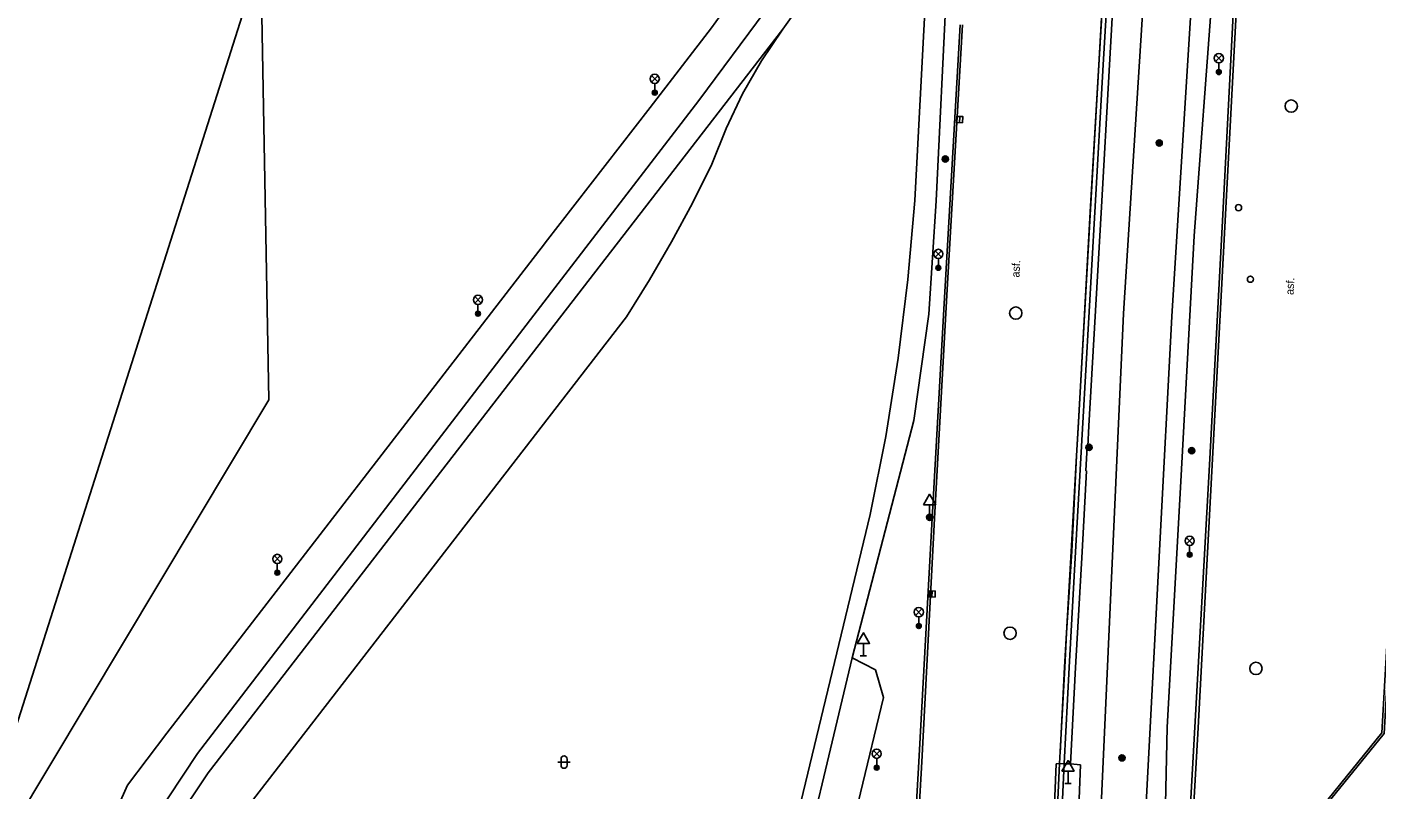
# Model space of a CAD drawing. Extents: x -599951 to -598963, y -1164095 to -1162939.
# Drawn here: x -599271.4 to -599161.8, y -1164038.6 to -1163976.7 of the extents above; entities that cross this region are included whole.
import ezdxf

# ---------------------------------------------------------------- set-up
doc = ezdxf.new("R2010")
doc.units = 0
for name, color, linetype in [('Level 10', 7, 'Continuous'), ('Level 11', 7, 'Continuous'), ('Level 13', 7, 'Continuous'), ('Level 25', 7, 'Continuous'), ('Level 27', 7, 'Continuous'), ('Level 28', 7, 'Continuous'), ('Level 33', 7, 'Continuous'), ('Level 34', 7, 'Continuous'), ('Level 36', 7, 'Continuous'), ('Level 40', 7, 'Continuous'), ('Level 9', 7, 'Continuous')]:
    doc.layers.add(name, color=color, linetype=linetype)

msp = doc.modelspace()

# ---------------------------------------------------------------- linework, layer by layer
at = {"layer": 'Level 10'}
for points in [[(-599173.23, -1163971.43), (-599174.29, -1163991.9), (-599175.35, -1164011.75), (-599176.55, -1164033.54), (-599177.56, -1164051.44), (-599178.64, -1164071.21)], [(-599196.92, -1163999.13), (-599195.62, -1163976.51)], [(-599196.92, -1163999.13), (-599197.89, -1164016.58)], [(-599159.94, -1164012.34), (-599161.18, -1164034.05), (-599165.51, -1164039.38)], [(-599197.89, -1164016.58), (-599198.98, -1164036.35), (-599199.45, -1164044.34), (-599199.93, -1164050.44), (-599200.67, -1164056.43), (-599201.53, -1164060.7), (-599202.85, -1164065), (-599204.64, -1164069.23), (-599206.88, -1164073.31), (-599208.33, -1164076.09), (-599209.5, -1164077.88), (-599210.81, -1164079.56), (-599212.22, -1164081.1), (-599214.37, -1164083.05)], [(-599190.59, -1164094.69), (-599190.42, -1164091.32), (-599188.5, -1164057.11), (-599187.54, -1164036.49)]]:
    msp.add_lwpolyline(points, dxfattribs=at)
at = {"layer": 'Level 11'}
for points in [[(-599172.9, -1163813.11), (-599173.38, -1163820.1), (-599174.07, -1163830.07), (-599174.74, -1163840.04), (-599175.4, -1163850), (-599175.95, -1163858.03), (-599176.47, -1163865.91), (-599177.1, -1163875.95), (-599177.75, -1163885.93), (-599178.52, -1163897.89), (-599179.3, -1163909.98), (-599179.92, -1163919.81), (-599180.51, -1163929.76), (-599181.12, -1163939.81), (-599181.72, -1163949.74), (-599182.32, -1163959.77), (-599182.91, -1163969.7), (-599183.49, -1163979.74), (-599184.17, -1163991.77), (-599185.17, -1164009.07), (-599185.26, -1164010.75)], [(-599172.9, -1163813.11), (-599173.38, -1163820.1), (-599174.07, -1163830.07), (-599174.74, -1163840.04), (-599175.4, -1163850), (-599175.95, -1163858.03), (-599176.47, -1163865.91), (-599177.1, -1163875.95), (-599177.75, -1163885.93), (-599178.52, -1163897.89), (-599179.3, -1163909.98), (-599179.92, -1163919.81), (-599180.51, -1163929.76), (-599181.12, -1163939.81), (-599181.72, -1163949.74), (-599182.32, -1163959.77), (-599182.91, -1163969.7), (-599183.49, -1163979.74), (-599184.17, -1163991.77), (-599185.17, -1164009.07), (-599185.26, -1164010.75)], [(-599186.16, -1164011.52), (-599186, -1164008.75), (-599185.03, -1163991.47), (-599184.35, -1163979.77), (-599183.76, -1163969.76), (-599183.18, -1163959.77), (-599182.58, -1163949.77), (-599181.98, -1163939.79), (-599181.35, -1163929.78), (-599180.76, -1163919.85), (-599180.56, -1163916.59)], [(-599173.97, -1163953.72), (-599175.11, -1163973.69), (-599176.62, -1163993.64)], [(-599288.18, -1164067.68), (-599277.59, -1164050.01), (-599272.53, -1164041.57), (-599251.79, -1164006.95), (-599252.73, -1163954.94)], [(-599288.18, -1164067.68), (-599277.59, -1164050.01), (-599272.53, -1164041.57), (-599251.79, -1164006.95), (-599252.73, -1163954.94)], [(-599272.69, -1163964.01), (-599294.28, -1164045.51), (-599277.59, -1164050.01), (-599252.44, -1163970.97)], [(-599178.38, -1164071.18), (-599177.31, -1164051.48), (-599176.3, -1164033.6), (-599175.12, -1164011.76), (-599174.06, -1163991.91), (-599172.98, -1163971.45)], [(-599196.72, -1163973.49), (-599197.56, -1163990.8), (-599198.17, -1163999.99)], [(-599247.79, -1164081.46), (-599251.56, -1164079.78), (-599256.02, -1164076.8), (-599259.29, -1164073.61), (-599262.33, -1164069.95), (-599264.74, -1164065.27), (-599266.14, -1164060.83), (-599266.79, -1164058.45), (-599267.31, -1164056.55), (-599267.39, -1164055.11), (-599267.51, -1164052.79), (-599267.55, -1164052.03), (-599267.32, -1164050.55), (-599266.92, -1164047.98), (-599265.6, -1164043.54), (-599263.26, -1164038.24), (-599260.07, -1164034.03), (-599229.39, -1163994.3), (-599229.33, -1163994.22), (-599220.81, -1163983.21), (-599215.82, -1163976.75), (-599214.4, -1163974.81)], [(-599247.79, -1164081.46), (-599251.56, -1164079.78), (-599256.02, -1164076.8), (-599259.29, -1164073.61), (-599262.33, -1164069.95), (-599264.74, -1164065.27), (-599266.14, -1164060.83), (-599266.79, -1164058.45), (-599267.31, -1164056.55), (-599267.39, -1164055.11), (-599267.51, -1164052.79), (-599267.55, -1164052.03), (-599267.32, -1164050.55), (-599266.92, -1164047.98), (-599265.6, -1164043.54), (-599263.26, -1164038.24), (-599260.07, -1164034.03), (-599229.39, -1163994.3), (-599229.33, -1163994.22), (-599220.81, -1163983.21), (-599215.82, -1163976.75), (-599214.4, -1163974.81)], [(-599211.47, -1163975.39), (-599216.86, -1163982.64), (-599230.24, -1164000.07), (-599257.58, -1164035.67), (-599261.16, -1164041.12), (-599262.87, -1164045.41), (-599264.04, -1164049.93), (-599264.28, -1164054.68), (-599263.81, -1164059.27), (-599262.56, -1164063.71), (-599259.99, -1164068.39), (-599256.72, -1164072.83), (-599254.73, -1164074.44)], [(-599195.43, -1163976.51), (-599196.69, -1163998.47)], [(-599176.62, -1163993.64), (-599177.69, -1164013.59), (-599178.8, -1164033.53)], [(-599197.7, -1164016.59), (-599196.69, -1163998.47)], [(-599198.17, -1163999.99), (-599199.37, -1164008.64), (-599204.39, -1164027.91)], [(-599185.41, -1164012.73), (-599185.31, -1164010.75)], [(-599185.26, -1164010.75), (-599185.31, -1164010.75)], [(-599186.97, -1164025.89), (-599186.6, -1164019.28), (-599186.16, -1164011.52)], [(-599165.72, -1164039.39), (-599161.36, -1164033.99), (-599160.13, -1164012.32)], [(-599185.36, -1164012.73), (-599185.72, -1164019.29), (-599186.25, -1164028.71), (-599186.67, -1164036.53)], [(-599185.36, -1164012.73), (-599185.41, -1164012.73)], [(-599197.7, -1164016.59), (-599198.73, -1164036.37), (-599199.2, -1164044.36)], [(-599187.54, -1164036.49), (-599187.12, -1164028.69), (-599186.97, -1164025.89)], [(-599209.56, -1164049.62), (-599204.39, -1164027.91)], [(-599202.5, -1164028.88), (-599204.39, -1164027.91)], [(-599201.85, -1164031.13), (-599202.5, -1164028.88)], [(-599205.58, -1164046.62), (-599201.85, -1164031.13)], [(-599178.8, -1164033.53), (-599179.01, -1164043.52), (-599179.62, -1164053.5), (-599180.52, -1164073.51), (-599181.2, -1164093.53), (-599181.24, -1164094.69)], [(-599190.81, -1164094.69), (-599190.53, -1164089.3), (-599188.66, -1164057.07), (-599187.81, -1164036.53), (-599187.54, -1164036.49)], [(-599187.18, -1164036.51), (-599187.54, -1164036.49)], [(-599187.29, -1164073.1), (-599185.85, -1164036.61), (-599186.67, -1164036.53)], [(-599186.67, -1164036.53), (-599187.18, -1164036.51)]]:
    msp.add_lwpolyline(points, dxfattribs=at)
at = {"layer": 'Level 13'}
msp.add_line((-599186.64, -1164094.69), (-599182.35, -1163999.95), dxfattribs=at)
for points in [[(-599178.43, -1164000.2), (-599167.24, -1163821.2)], [(-599173.6, -1163862.17), (-599182.35, -1163999.95)], [(-599193.21, -1163875.57), (-599199.31, -1163990.76)], [(-599201.8, -1163953.59), (-599202.01, -1163956.72), (-599202.47, -1163959.82), (-599203.16, -1163962.87), (-599204.09, -1163965.87), (-599205.25, -1163968.78), (-599206.63, -1163971.59), (-599208.22, -1163974.29), (-599210.02, -1163976.85)], [(-599210.02, -1163976.85), (-599256.7, -1164037.24)], [(-599210.02, -1163976.85), (-599211.75, -1163979.43), (-599213.3, -1163982.12), (-599214.64, -1163984.92), (-599215.78, -1163987.81), (-599217.37, -1163990.99), (-599219.06, -1163994.12), (-599220.85, -1163997.2), (-599222.73, -1164000.22)], [(-599202.93, -1164016.26), (-599201.67, -1164009.94), (-599200.65, -1164003.58), (-599199.86, -1163997.18), (-599199.31, -1163990.76)], [(-599253.47, -1164039.98), (-599222.73, -1164000.22)], [(-599181.42, -1164057.19), (-599178.43, -1164000.2)], [(-599210.01, -1164045.6), (-599202.93, -1164016.26)], [(-599212.79, -1164057.11), (-599213.94, -1164061.16), (-599215.67, -1164064.99), (-599217.96, -1164068.51), (-599220.74, -1164071.67), (-599223.96, -1164074.37), (-599227.54, -1164076.56), (-599231.41, -1164078.2), (-599235.49, -1164079.25), (-599240.42, -1164078.89), (-599245.24, -1164077.72), (-599249.79, -1164075.77), (-599253.95, -1164073.08), (-599257.29, -1164069.43), (-599259.89, -1164065.22), (-599261.64, -1164060.59), (-599262.49, -1164055.71), (-599262.4, -1164050.76), (-599261.37, -1164045.92), (-599259.45, -1164041.35), (-599256.7, -1164037.24)]]:
    msp.add_lwpolyline(points, dxfattribs=at)
at = {"layer": 'Level 25'}
for centre, radius in [((-599179.45, -1163986.1), 0.25), ((-599179.45, -1163986.1), 0.2), ((-599179.45, -1163986.1), 0.15), ((-599179.45, -1163986.1), 0.1), ((-599179.45, -1163986.1), 0.05), ((-599196.83, -1163987.4), 0.25), ((-599196.83, -1163987.4), 0.2), ((-599196.83, -1163987.4), 0.15), ((-599196.83, -1163987.4), 0.1), ((-599196.83, -1163987.4), 0.05), ((-599185.15, -1164010.82), 0.25), ((-599185.15, -1164010.82), 0.2), ((-599185.15, -1164010.82), 0.15), ((-599185.15, -1164010.82), 0.1), ((-599185.15, -1164010.82), 0.05), ((-599176.81, -1164011.09), 0.25), ((-599176.81, -1164011.09), 0.2), ((-599176.81, -1164011.09), 0.15), ((-599176.81, -1164011.09), 0.1), ((-599176.81, -1164011.09), 0.05), ((-599198.1, -1164016.5), 0.25), ((-599198.1, -1164016.5), 0.2), ((-599198.1, -1164016.5), 0.15), ((-599198.1, -1164016.5), 0.1), ((-599198.1, -1164016.5), 0.05), ((-599182.48, -1164036.04), 0.25), ((-599182.48, -1164036.04), 0.2), ((-599182.48, -1164036.04), 0.15), ((-599182.48, -1164036.04), 0.1), ((-599182.48, -1164036.04), 0.05)]:
    msp.add_circle(centre, radius, dxfattribs=at)
at = {"layer": 'Level 27'}
for p, q in [((-599195.67, -1163984.45), (-599195.65, -1163983.95)), ((-599197.91, -1164022.98), (-599197.89, -1164022.48))]:
    msp.add_line(p, q, dxfattribs=at)
for points in [[(-599195.42, -1163984.46), (-599195.4, -1163983.96), (-599195.9, -1163983.94), (-599195.92, -1163984.44)], [(-599197.66, -1164022.99), (-599197.64, -1164022.49), (-599198.14, -1164022.47), (-599198.16, -1164022.97)]]:
    msp.add_lwpolyline(points, close=True, dxfattribs=at)
for centre in [(-599168.73, -1163983.1), (-599191.1, -1163999.91), (-599191.57, -1164025.91), (-599171.59, -1164028.77)]:
    msp.add_circle(centre, 0.5, dxfattribs=at)
at = {"layer": 'Level 28'}
for centre in [(-599173.01, -1163991.35), (-599172.04, -1163997.16)]:
    msp.add_circle(centre, 0.25, dxfattribs=at)
at = {"layer": 'Level 33'}
for p, q in [((-599174.87, -1163979.48), (-599174.34, -1163978.95)), ((-599174.87, -1163978.95), (-599174.34, -1163979.48)), ((-599220.69, -1163981.15), (-599220.16, -1163980.62)), ((-599220.69, -1163980.62), (-599220.16, -1163981.15)), ((-599174.61, -1163979.59), (-599174.61, -1163980.34)), ((-599220.43, -1163981.26), (-599220.43, -1163982.01)), ((-599197.66, -1163995.38), (-599197.13, -1163994.85)), ((-599197.66, -1163994.85), (-599197.13, -1163995.38)), ((-599197.39, -1163995.49), (-599197.39, -1163996.24)), ((-599235.05, -1163999.1), (-599234.52, -1163998.57)), ((-599235.05, -1163998.57), (-599234.52, -1163999.1)), ((-599234.79, -1163999.21), (-599234.79, -1163999.96)), ((-599177.25, -1164018.67), (-599176.72, -1164018.14)), ((-599177.25, -1164018.14), (-599176.72, -1164018.67)), ((-599176.98, -1164018.78), (-599176.98, -1164019.53)), ((-599251.35, -1164020.14), (-599250.82, -1164019.61)), ((-599251.35, -1164019.61), (-599250.82, -1164020.14)), ((-599251.09, -1164020.25), (-599251.09, -1164021)), ((-599199.25, -1164024.47), (-599198.72, -1164023.94)), ((-599199.25, -1164023.94), (-599198.72, -1164024.47)), ((-599198.98, -1164024.58), (-599198.98, -1164025.33)), ((-599202.66, -1164035.97), (-599202.13, -1164035.44)), ((-599202.66, -1164035.44), (-599202.13, -1164035.97)), ((-599202.4, -1164036.08), (-599202.4, -1164036.83))]:
    msp.add_line(p, q, dxfattribs=at)
for centre, radius in [((-599174.61, -1163979.21), 0.375), ((-599220.43, -1163980.89), 0.375), ((-599174.61, -1163980.34), 0.2), ((-599174.61, -1163980.34), 0.145), ((-599174.61, -1163980.34), 0.0876), ((-599220.43, -1163982.01), 0.2), ((-599220.43, -1163982.01), 0.145), ((-599220.43, -1163982.01), 0.0876), ((-599197.39, -1163995.11), 0.375), ((-599197.39, -1163996.24), 0.2), ((-599197.39, -1163996.24), 0.145), ((-599197.39, -1163996.24), 0.0876), ((-599234.79, -1163998.84), 0.375), ((-599234.79, -1163999.96), 0.2), ((-599234.79, -1163999.96), 0.145), ((-599234.79, -1163999.96), 0.0876), ((-599176.98, -1164018.41), 0.375), ((-599251.09, -1164019.88), 0.375), ((-599176.98, -1164019.53), 0.2), ((-599176.98, -1164019.53), 0.145), ((-599176.98, -1164019.53), 0.0876), ((-599251.09, -1164021), 0.2), ((-599251.09, -1164021), 0.145), ((-599251.09, -1164021), 0.0876), ((-599198.98, -1164024.2), 0.375), ((-599198.98, -1164025.33), 0.2), ((-599198.98, -1164025.33), 0.145), ((-599198.98, -1164025.33), 0.0876), ((-599202.4, -1164035.7), 0.375), ((-599202.4, -1164036.83), 0.2), ((-599202.4, -1164036.83), 0.145), ((-599202.4, -1164036.83), 0.0876)]:
    msp.add_circle(centre, radius, dxfattribs=at)
at = {"layer": 'Level 34'}
for p, q in [((-599198.1, -1164015.48), (-599198.1, -1164016.5)), ((-599198.35, -1164016.5), (-599197.85, -1164016.5)), ((-599203.73, -1164027.76), (-599203.23, -1164027.76)), ((-599203.48, -1164026.74), (-599203.48, -1164027.76)), ((-599186.86, -1164037.11), (-599186.86, -1164038.13)), ((-599187.11, -1164038.13), (-599186.61, -1164038.13))]:
    msp.add_line(p, q, dxfattribs=at)
for points in [[(-599198.6, -1164015.48), (-599197.6, -1164015.48), (-599198.1, -1164014.62)], [(-599203.98, -1164026.74), (-599202.98, -1164026.74), (-599203.48, -1164025.88)], [(-599187.36, -1164037.11), (-599186.36, -1164037.11), (-599186.86, -1164036.25)]]:
    msp.add_lwpolyline(points, close=True, dxfattribs=at)
at = {"layer": 'Level 36'}
for p, q in [((-599228.29, -1164036.38), (-599227.29, -1164036.38)), ((-599228.04, -1164036.13), (-599228.04, -1164036.63)), ((-599227.54, -1164036.13), (-599227.54, -1164036.63))]:
    msp.add_line(p, q, dxfattribs=at)
for centre, start, end in [((-599227.79, -1164036.13), 0, 180), ((-599227.79, -1164036.63), 180, 0)]:
    msp.add_arc(centre, 0.25, start, end, dxfattribs=at)
at = {"layer": 'Level 9'}
for points in [[(-599173.33, -1163813.06), (-599173.85, -1163820.02), (-599174.57, -1163830.04), (-599175.22, -1163839.98), (-599175.88, -1163849.93), (-599176.42, -1163857.97), (-599177.03, -1163867.36), (-599177.61, -1163875.9), (-599178.24, -1163885.85), (-599178.98, -1163897.83), (-599179.77, -1163909.83), (-599180.41, -1163919.76), (-599181.02, -1163929.73), (-599181.63, -1163939.74), (-599182.23, -1163949.69), (-599182.82, -1163959.75), (-599183.42, -1163969.73), (-599184.01, -1163979.76), (-599184.69, -1163991.72), (-599185.65, -1164008.82), (-599186.25, -1164019.31), (-599186.77, -1164028.71), (-599187.18, -1164036.5)], [(-599173.33, -1163813.06), (-599173.85, -1163820.02), (-599174.57, -1163830.04), (-599175.22, -1163839.98), (-599175.88, -1163849.93), (-599176.42, -1163857.97), (-599177.03, -1163867.36), (-599177.61, -1163875.9), (-599178.24, -1163885.85), (-599178.98, -1163897.83), (-599179.77, -1163909.83), (-599180.41, -1163919.76), (-599181.02, -1163929.73), (-599181.63, -1163939.74), (-599182.23, -1163949.69), (-599182.82, -1163959.75), (-599183.42, -1163969.73), (-599184.01, -1163979.76), (-599184.69, -1163991.72), (-599185.65, -1164008.82), (-599186.25, -1164019.31), (-599186.77, -1164028.71), (-599187.18, -1164036.5)], [(-599180.61, -1163916.55), (-599180.74, -1163919.06), (-599181.39, -1163929.71), (-599182, -1163939.72), (-599182.6, -1163949.67), (-599183.19, -1163959.73), (-599183.79, -1163969.7), (-599184.36, -1163979.74), (-599185.06, -1163991.7), (-599186.02, -1164008.8), (-599186.16, -1164011.52)], [(-599186.16, -1164011.52), (-599186.55, -1164019.26), (-599186.97, -1164025.89)], [(-599186.97, -1164025.89), (-599187.14, -1164028.68), (-599187.51, -1164035.66)], [(-599190.23, -1164094.69), (-599190.07, -1164091.34), (-599188.15, -1164057.12), (-599187.18, -1164036.51)], [(-599187.18, -1164036.51), (-599187.18, -1164036.5)]]:
    msp.add_lwpolyline(points, dxfattribs=at)

# ---------------------------------------------------------------- texts
at = {"layer": 'Level 40'}
for p in [(-599190.81, -1163997.03), (-599168.54, -1163998.45)]:
    msp.add_text('asf.', height=0.65, rotation=87.1, dxfattribs=at).set_placement(p)

doc.saveas('drawing.dxf')
